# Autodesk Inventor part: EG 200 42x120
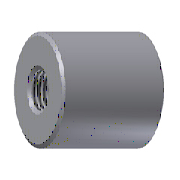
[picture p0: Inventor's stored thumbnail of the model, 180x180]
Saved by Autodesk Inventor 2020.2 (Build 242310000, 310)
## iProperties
Manager: www.cadconsulting.pl
Company: Fabian Stasiak CAD Consulting
Created: 2014-02
Part Number: EG 200 42x120
Material: DIN 1.7131
Description: Locating sleeves
Document SubType Name: Modeling
Designer: F.Stasiak
Standard Revision: 1
Manufacturer: DME
Language: pl-PL
Size Designation: 42x120
Categories: <MemberInstance><Categories><Category DisplayName="Forma wtryskowa" InternalName="349578f2-f4d4-4954-8c09-8e99297a61c0" Mnemonic="MOLD"><Category DisplayName="E
Mass: 1.68626 g
Surface Area: 16.3679 cm^2
Volume: 1.68626 cm^3
Density: 7.85 g/cm^3
Appearance: Stal
Catalog Web Link: www.expertbooks.pl
IsCustomPart: 0
Author: F.Stasiak
Subject: Zbiór ćwiczeń. Autodesk Inventor 2020. Kurs Professional
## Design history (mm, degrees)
sketch "Sketch1"
  geometry: L1 (0, -144)-(0, 24) reference; L2 (0, 0)-(21, 0); L3 (21, 0)-(21, -2.5); L4 (21, -2.5)-(20.987, -2.5); L5 (20.987, -2.5)-(20.988, -120); L6 (20.988, -120)-(16.5, -120); L7 (16.5, -120)-(16.5, -13); L8 (16.5, -13)-(8, -11); L9 (8, -11)-(0, -11); L10 (0, 0)-(0, -11); 1 further point
  constraints: 18 end point, 4 parallel, 3 perpendicular, 2 point on line, 1 coincident, 1 collinear
  dimensions: "d0" = 42 diameter of L3 L1 (= D); "d2" = 42 dimension on L5 L1 (= D_Guide); "d4" = 120 distance between parallel lines of L6 L2 (= L); "d5" = 33 diameter of L7 L1 (= d_); "d6" = 13 distance from line of L7.end L2 (= L1); "d7" = 2 distance from line of L7.end L9; "d8" = 16 diameter of L8.end L1 (= M); "d33" = 2.5 distance between parallel lines of L2 L4 (= L2)
revolve "Revolution1" sketch "Sketch1" stored, may be unused: angle "d9" = 90 deg
sketch "Sketch2"
  geometry: 1 further point
hole "Hole1" sketch "Sketch2" at (0, 0) diameter "d10" = 13.835; stored, may be unused: countersink angle "d14" = 90 deg, drill point angle "d16" = 0 deg; dims "d11" = 6, "d12" = 4, "d13" = 2, "d15" = 120 (= L)
chamfer "Chamfer1" distance "d17" = 0.5; stored, may be unused: second distance "d18" = 2, angle "d19" = 45 deg
fillet "Fillet1" dims "d30" = 0.5
body "Solid1"
other parameters: "D" = 42 [user parameter; used in 1 equation term], "L" = 120 [user parameter; used in 2 equation terms], "d_" = 33 [user parameter; used in 1 equation term], "M" = 16 [user parameter; used in 1 equation term], "L1" = 13 [user parameter; used in 1 equation term], "d22" = 0, "D_Guide" = 42 [user parameter; used in 1 equation term], "d31" = 0, "d32" = 0, "L2" = 2.5 [user parameter; used in 1 equation term]
